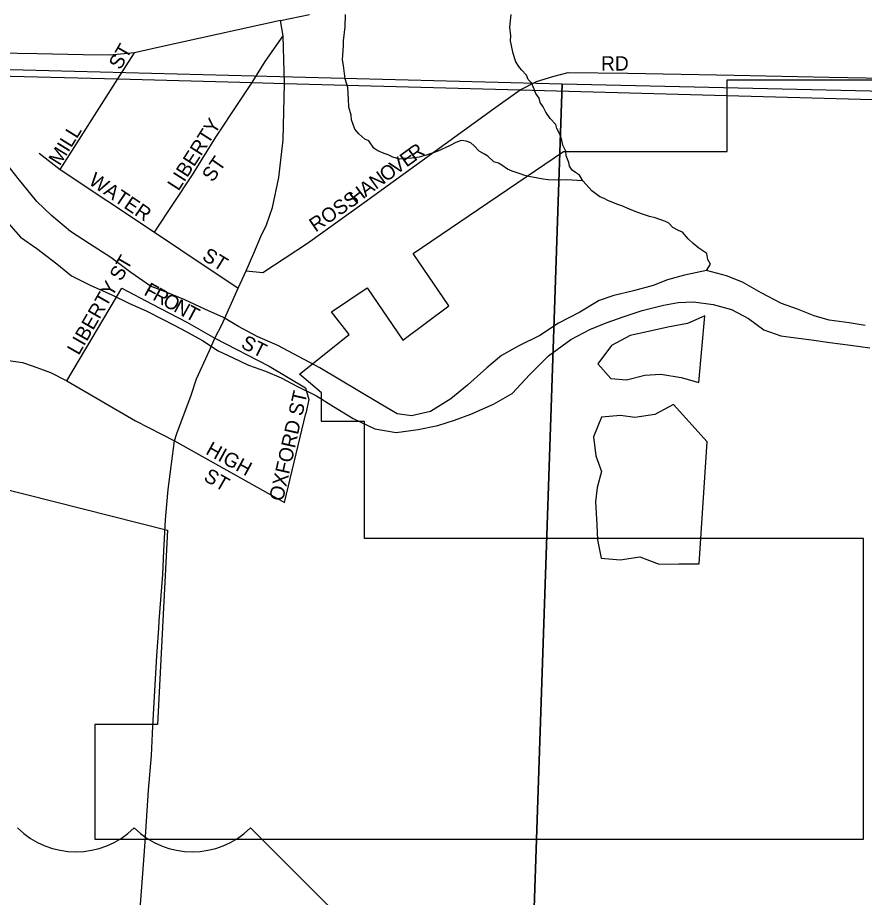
# Model space of a CAD drawing. Extents: x 0 to 34, y -2.3 to 22.
# Drawn here: x 5.063 to 5.622, y 19.85 to 20.43 of the extents above; entities that cross this region are included whole.
import ezdxf

# ---------------------------------------------------------------- set-up
doc = ezdxf.new("R2010")
doc.units = 0
for name, color, linetype in [('GM_X_City_Street', 7, 'Continuous'), ('GM_X_City_Street_Text', 7, 'Continuous'), ('GM_X_Corporation', 7, 'Continuous'), ('GM_X_Major_River', 7, 'Continuous'), ('GM_X_Minor_Lake', 7, 'Continuous'), ('GM_X_Minor_River', 7, 'Continuous'), ('GM_X_Section', 7, 'Continuous'), ('GM_X_State_Route', 7, 'Continuous'), ('GM_X_Township', 7, 'Continuous'), ('GM_X_US_Route', 7, 'Continuous'), ('GM_X_US_Shield', 7, 'Continuous')]:
    doc.layers.add(name, color=color, linetype=linetype)

msp = doc.modelspace()

# ---------------------------------------------------------------- linework, layer by layer
at = {"layer": 'GM_X_City_Street'}
for p, q in [((5.22626, 20.40134), (5.23811, 20.41837)), ((5.12886, 20.38988), (5.13988, 20.40723)), ((5.21759, 20.38745), (5.22626, 20.40134)), ((5.41612, 20.39156), (5.42625, 20.39407)), ((5.42625, 20.39407), (5.46566, 20.39379)), ((5.46566, 20.39379), (5.53591, 20.3924)), ((5.09095, 20.33019), (5.12886, 20.38988)), ((5.39462, 20.38262), (5.40534, 20.38813)), ((5.40534, 20.38813), (5.41612, 20.39156)), ((5.53591, 20.3924), (5.59864, 20.3911)), ((5.59864, 20.3911), (5.6453, 20.39026)), ((5.20883, 20.37426), (5.21759, 20.38745)), ((5.377, 20.37028), (5.39462, 20.38262)), ((5.19362, 20.3514), (5.20883, 20.37426)), ((5.29159, 20.30839), (5.377, 20.37028)), ((5.17831, 20.32653), (5.19362, 20.3514)), ((5.07696, 20.34097), (5.09095, 20.33019)), ((5.09095, 20.33019), (5.15323, 20.28879)), ((5.15323, 20.28879), (5.17831, 20.32653)), ((5.25414, 20.28162), (5.29159, 20.30839)), ((5.15323, 20.28879), (5.17052, 20.2771)), ((5.22477, 20.2622), (5.25414, 20.28162)), ((5.17052, 20.2771), (5.2084, 20.25188)), ((5.21369, 20.26322), (5.22477, 20.2622)), ((5.09518, 20.19062), (5.13161, 20.2519)), ((5.13161, 20.2519), (5.1517, 20.24133)), ((5.1517, 20.24133), (5.1744, 20.22938)), ((5.1744, 20.22938), (5.19304, 20.21874)), ((5.19304, 20.21874), (5.22879, 20.20028)), ((5.22879, 20.20028), (5.25287, 20.18608)), ((5.25287, 20.18608), (5.25512, 20.17828)), ((5.25512, 20.17828), (5.25303, 20.16909)), ((5.23903, 20.11025), (5.25303, 20.16909)), ((5.16643, 20.15101), (5.23903, 20.11025))]:
    msp.add_line(p, q, dxfattribs=at)
at = {"layer": 'GM_X_Corporation'}
for p, q in [((5.53117, 20.34201), (5.53118, 20.38935)), ((5.53118, 20.38935), (5.66754, 20.38934)), ((5.32391, 20.2747), (5.42322, 20.34201)), ((5.42322, 20.34201), (5.53117, 20.34201)), ((5.34741, 20.24023), (5.32391, 20.2747)), ((5.26993, 20.23619), (5.29361, 20.25198)), ((5.29361, 20.25198), (5.31711, 20.21751)), ((5.31711, 20.21751), (5.34741, 20.24023)), ((5.28163, 20.22123), (5.26993, 20.23619)), ((5.24886, 20.19501), (5.28163, 20.22123)), ((5.26347, 20.1828), (5.24886, 20.19501)), ((5.26347, 20.16386), (5.26347, 20.1828)), ((5.29188, 20.16386), (5.26347, 20.16386)), ((5.29187, 20.08661), (5.29188, 20.16386)), ((4.9456, 20.14662), (5.16168, 20.09204)), ((5.16168, 20.09204), (5.15509, 19.96389)), ((5.62136, 20.08659), (5.29187, 20.08661)), ((5.62134, 19.88812), (5.62136, 20.08659)), ((5.11381, 19.96389), (5.1138, 19.88814)), ((5.15509, 19.96389), (5.11381, 19.96389)), ((5.1138, 19.88814), (5.62134, 19.88812))]:
    msp.add_line(p, q, dxfattribs=at)
at = {"layer": 'GM_X_Major_River'}
for p, q in [((5.06314, 20.32417), (5.05352, 20.33652)), ((5.07536, 20.3091), (5.06314, 20.32417)), ((5.08505, 20.29978), (5.07536, 20.3091)), ((5.05385, 20.29776), (5.06461, 20.28539)), ((5.09775, 20.28926), (5.08505, 20.29978)), ((5.11011, 20.28103), (5.09775, 20.28926)), ((5.06461, 20.28539), (5.07547, 20.27794)), ((5.07547, 20.27794), (5.08855, 20.2678)), ((5.12436, 20.272), (5.11011, 20.28103)), ((5.13746, 20.26224), (5.12436, 20.272)), ((5.08855, 20.2678), (5.09827, 20.26)), ((5.09827, 20.26), (5.11106, 20.25366)), ((5.15057, 20.25323), (5.13746, 20.26224)), ((5.50298, 20.26044), (5.4919, 20.25725)), ((5.51749, 20.26356), (5.50298, 20.26044)), ((5.53071, 20.25987), (5.51749, 20.26356)), ((5.4919, 20.25725), (5.48232, 20.25364)), ((5.54127, 20.25585), (5.53071, 20.25987)), ((5.55366, 20.24876), (5.54127, 20.25585)), ((5.11106, 20.25366), (5.12461, 20.24768)), ((5.16074, 20.24922), (5.15057, 20.25323)), ((5.17318, 20.24403), (5.16074, 20.24922)), ((5.46933, 20.25011), (5.45634, 20.24696)), ((5.48232, 20.25364), (5.46933, 20.25011)), ((5.56719, 20.24165), (5.55366, 20.24876)), ((5.12461, 20.24768), (5.13665, 20.24174)), ((5.18635, 20.23806), (5.17318, 20.24403)), ((5.44677, 20.24374), (5.43407, 20.23602)), ((5.45634, 20.24696), (5.44677, 20.24374)), ((5.4988, 20.24229), (5.50907, 20.24284)), ((5.50907, 20.24284), (5.52196, 20.24105)), ((5.13665, 20.24174), (5.14757, 20.23696)), ((5.14757, 20.23696), (5.15884, 20.23103)), ((5.19877, 20.23249), (5.18635, 20.23806)), ((5.46327, 20.23314), (5.47513, 20.23708)), ((5.47513, 20.23708), (5.48927, 20.24059)), ((5.48927, 20.24059), (5.4988, 20.24229)), ((5.52196, 20.24105), (5.53405, 20.23777)), ((5.53405, 20.23777), (5.54532, 20.23184)), ((5.57775, 20.23801), (5.56719, 20.24165)), ((5.58868, 20.23361), (5.57775, 20.23801)), ((5.15884, 20.23103), (5.17125, 20.22469)), ((5.20853, 20.22659), (5.19877, 20.23249)), ((5.43407, 20.23602), (5.41985, 20.22871)), ((5.4514, 20.22883), (5.46327, 20.23314)), ((5.54532, 20.23184), (5.55543, 20.22441)), ((5.5985, 20.23075), (5.58868, 20.23361)), ((5.22093, 20.21988), (5.20853, 20.22659)), ((5.41985, 20.22871), (5.40752, 20.22061)), ((5.44067, 20.22449), (5.4514, 20.22883)), ((5.61176, 20.22896), (5.5985, 20.23075)), ((5.62236, 20.22722), (5.61176, 20.22896)), ((5.17125, 20.22469), (5.18477, 20.2172)), ((5.23448, 20.2139), (5.22093, 20.21988)), ((5.40752, 20.22061), (5.3937, 20.21367)), ((5.42799, 20.21791), (5.44067, 20.22449)), ((5.55543, 20.22441), (5.56674, 20.22038)), ((5.56674, 20.22038), (5.57659, 20.21904)), ((5.18477, 20.2172), (5.19527, 20.21053)), ((5.26229, 20.19927), (5.23448, 20.2139)), ((5.3937, 20.21367), (5.38217, 20.20745)), ((5.41332, 20.20719), (5.42799, 20.21791)), ((5.57659, 20.21904), (5.58682, 20.21769)), ((5.58682, 20.21769), (5.59895, 20.21592)), ((5.59895, 20.21592), (5.61259, 20.21412)), ((5.61259, 20.21412), (5.62547, 20.21234)), ((5.19527, 20.21053), (5.20505, 20.20577)), ((5.20505, 20.20577), (5.21521, 20.201)), ((5.38217, 20.20745), (5.3725, 20.19929)), ((5.4009, 20.19491), (5.41332, 20.20719)), ((5.21521, 20.201), (5.22653, 20.19697)), ((5.22653, 20.19697), (5.23669, 20.19258)), ((5.28856, 20.18354), (5.26229, 20.19927)), ((5.3725, 20.19929), (5.35971, 20.18778)), ((5.23669, 20.19258), (5.24721, 20.18705)), ((5.38924, 20.18223), (5.4009, 20.19491)), ((5.24721, 20.18705), (5.26, 20.18071)), ((5.35971, 20.18778), (5.34888, 20.17888)), ((5.26, 20.18071), (5.27125, 20.17364)), ((5.30095, 20.17607), (5.28856, 20.18354)), ((5.34888, 20.17888), (5.33541, 20.17042)), ((5.37693, 20.17527), (5.38924, 20.18223)), ((5.27125, 20.17364), (5.28439, 20.16577)), ((5.31333, 20.16897), (5.30095, 20.17607)), ((5.36197, 20.16874), (5.37693, 20.17527)), ((5.32281, 20.16764), (5.31333, 20.16897)), ((5.33541, 20.17042), (5.32281, 20.16764)), ((5.35125, 20.16478), (5.36197, 20.16874)), ((5.28439, 20.16577), (5.29869, 20.15902)), ((5.32718, 20.15843), (5.34015, 20.16121)), ((5.34015, 20.16121), (5.35125, 20.16478)), ((5.29869, 20.15902), (5.31269, 20.15645)), ((5.31269, 20.15645), (5.32718, 20.15843))]:
    msp.add_line(p, q, dxfattribs=at)
at = {"layer": 'GM_X_Minor_Lake'}
for p, q in [((5.51648, 20.23357), (5.50497, 20.22849)), ((5.51251, 20.18958), (5.51648, 20.23357)), ((5.492, 20.22609), (5.4794, 20.22331)), ((5.50497, 20.22849), (5.492, 20.22609)), ((5.46718, 20.22052), (5.45488, 20.21394)), ((5.4794, 20.22331), (5.46718, 20.22052)), ((5.45488, 20.21394), (5.44589, 20.20196)), ((5.44589, 20.20196), (5.45443, 20.19229)), ((5.45443, 20.19229), (5.46467, 20.19132)), ((5.46467, 20.19132), (5.47689, 20.19449)), ((5.47689, 20.19449), (5.48755, 20.19503)), ((5.48755, 20.19503), (5.5008, 20.19286)), ((5.5008, 20.19286), (5.51251, 20.18958)), ((5.49587, 20.17511), (5.48357, 20.16852)), ((5.51814, 20.15034), (5.49587, 20.17511)), ((5.46075, 20.16785), (5.44819, 20.16659)), ((5.47023, 20.16652), (5.46075, 20.16785)), ((5.48357, 20.16852), (5.47023, 20.16652)), ((5.44819, 20.16659), (5.44298, 20.15378)), ((5.44298, 20.15378), (5.44461, 20.14121)), ((5.51265, 20.06991), (5.51814, 20.15034)), ((5.44461, 20.14121), (5.44819, 20.13088)), ((5.44819, 20.13088), (5.44531, 20.1203)), ((5.44531, 20.1203), (5.44435, 20.11082)), ((5.44435, 20.11082), (5.44517, 20.09561)), ((5.44517, 20.09561), (5.44572, 20.08572)), ((5.44572, 20.08572), (5.44813, 20.07351)), ((5.46064, 20.0725), (5.47361, 20.07451)), ((5.47361, 20.07451), (5.48643, 20.06969)), ((5.44813, 20.07351), (5.46064, 20.0725)), ((5.48643, 20.06969), (5.49935, 20.0698)), ((5.49935, 20.0698), (5.51265, 20.06991))]:
    msp.add_line(p, q, dxfattribs=at)
at = {"layer": 'GM_X_Minor_River'}
for p, q in [((5.27897, 20.42419), (5.27916, 20.43254)), ((5.38773, 20.42414), (5.38868, 20.43247)), ((5.278, 20.41509), (5.27897, 20.42419)), ((5.38836, 20.41842), (5.38773, 20.42414)), ((5.38828, 20.415), (5.38836, 20.41842)), ((5.27739, 20.40561), (5.27792, 20.41206)), ((5.27792, 20.41206), (5.278, 20.41509)), ((5.38998, 20.40661), (5.38828, 20.415)), ((5.27732, 20.40257), (5.27739, 20.40561)), ((5.39176, 20.40124), (5.38998, 20.40661)), ((5.278, 20.39876), (5.27732, 20.40257)), ((5.39359, 20.39816), (5.39176, 20.40124)), ((5.27863, 20.39342), (5.278, 20.39876)), ((5.39544, 20.39583), (5.39359, 20.39816)), ((5.39878, 20.39233), (5.39544, 20.39583)), ((5.27893, 20.39), (5.27863, 20.39342)), ((5.2807, 20.38426), (5.27893, 20.39)), ((5.39986, 20.38964), (5.39878, 20.39233)), ((5.40209, 20.38731), (5.39986, 20.38964)), ((5.28128, 20.37664), (5.2807, 20.38426)), ((5.40389, 20.38309), (5.40209, 20.38731)), ((5.40497, 20.3804), (5.40389, 20.38309)), ((5.28154, 20.37132), (5.28128, 20.37664)), ((5.40718, 20.37731), (5.40497, 20.3804)), ((5.40787, 20.37425), (5.40718, 20.37731)), ((5.28294, 20.36597), (5.28154, 20.37132)), ((5.40971, 20.37154), (5.40787, 20.37425)), ((5.41153, 20.36808), (5.40971, 20.37154)), ((5.28325, 20.36292), (5.28294, 20.36597)), ((5.41447, 20.36383), (5.41153, 20.36808)), ((5.28539, 20.35679), (5.28325, 20.36292)), ((5.41818, 20.35994), (5.41447, 20.36383)), ((5.41888, 20.35726), (5.41818, 20.35994)), ((5.28798, 20.35369), (5.28539, 20.35679)), ((5.29208, 20.35016), (5.28798, 20.35369)), ((5.42069, 20.35342), (5.41888, 20.35726)), ((5.42213, 20.34958), (5.42069, 20.35342)), ((5.29471, 20.34896), (5.29208, 20.35016)), ((5.29803, 20.34432), (5.29471, 20.34896)), ((5.35211, 20.34791), (5.34788, 20.34574)), ((5.35557, 20.34934), (5.35211, 20.34791)), ((5.35898, 20.34888), (5.35557, 20.34934)), ((5.362, 20.34766), (5.35898, 20.34888)), ((5.36423, 20.34571), (5.362, 20.34766)), ((5.42281, 20.34615), (5.42213, 20.34958)), ((5.30064, 20.34235), (5.29803, 20.34432)), ((5.30479, 20.34073), (5.30064, 20.34235)), ((5.34019, 20.34213), (5.33712, 20.34106)), ((5.34788, 20.34574), (5.34019, 20.34213)), ((5.36757, 20.34221), (5.36423, 20.34571)), ((5.37095, 20.34022), (5.36757, 20.34221)), ((5.42462, 20.3423), (5.42281, 20.34615)), ((5.42493, 20.33926), (5.42462, 20.3423)), ((5.30743, 20.3399), (5.30479, 20.34073)), ((5.31044, 20.33831), (5.30743, 20.3399)), ((5.31497, 20.33706), (5.31044, 20.33831)), ((5.31764, 20.33737), (5.31497, 20.33706)), ((5.32297, 20.33762), (5.31764, 20.33737)), ((5.32793, 20.33825), (5.32297, 20.33762)), ((5.33253, 20.33966), (5.32793, 20.33825)), ((5.33712, 20.34106), (5.33253, 20.33966)), ((5.3732, 20.33903), (5.37095, 20.34022)), ((5.37729, 20.33512), (5.3732, 20.33903)), ((5.42672, 20.33465), (5.42493, 20.33926)), ((5.38032, 20.33429), (5.37729, 20.33512)), ((5.38257, 20.33309), (5.38032, 20.33429)), ((5.38631, 20.33034), (5.38257, 20.33309)), ((5.38933, 20.32913), (5.38631, 20.33034)), ((5.42705, 20.33237), (5.42672, 20.33465)), ((5.42889, 20.32966), (5.42705, 20.33237)), ((5.43113, 20.32808), (5.42889, 20.32966)), ((5.39385, 20.32749), (5.38933, 20.32913)), ((5.39762, 20.32626), (5.39385, 20.32749)), ((5.40027, 20.32543), (5.39762, 20.32626)), ((5.40633, 20.32452), (5.40027, 20.32543)), ((5.40973, 20.32368), (5.40633, 20.32452)), ((5.43376, 20.3265), (5.43113, 20.32808)), ((5.43595, 20.32265), (5.43376, 20.3265)), ((5.41315, 20.32321), (5.40973, 20.32368)), ((5.42151, 20.32301), (5.41315, 20.32321)), ((5.42532, 20.32329), (5.42151, 20.32301)), ((5.43595, 20.32265), (5.42532, 20.32329)), ((5.43818, 20.32031), (5.43595, 20.32265)), ((5.44188, 20.31604), (5.43818, 20.32031)), ((5.44711, 20.31211), (5.44188, 20.31604)), ((5.45013, 20.3109), (5.44711, 20.31211)), ((5.45238, 20.3097), (5.45013, 20.3109)), ((5.45841, 20.30727), (5.45238, 20.3097)), ((5.4618, 20.30605), (5.45841, 20.30727)), ((5.4667, 20.30403), (5.4618, 20.30605)), ((5.47047, 20.30241), (5.4667, 20.30403)), ((5.47461, 20.30079), (5.47047, 20.30241)), ((5.4799, 20.29914), (5.47461, 20.30079)), ((5.48368, 20.29829), (5.4799, 20.29914)), ((5.49047, 20.29584), (5.48368, 20.29829)), ((5.49272, 20.29464), (5.49047, 20.29584)), ((5.49532, 20.29192), (5.49272, 20.29464)), ((5.49908, 20.28992), (5.49532, 20.29192)), ((5.50171, 20.28872), (5.49908, 20.28992)), ((5.50542, 20.28445), (5.50171, 20.28872)), ((5.50877, 20.28132), (5.50542, 20.28445)), ((5.5125, 20.27819), (5.50877, 20.28132)), ((5.51774, 20.27464), (5.5125, 20.27819)), ((5.51841, 20.27083), (5.51774, 20.27464)), ((5.51749, 20.26356), (5.52024, 20.26774)), ((5.52024, 20.26774), (5.51841, 20.27083))]:
    msp.add_line(p, q, dxfattribs=at)
at = {"layer": 'GM_X_Section'}
for p, q in [((4.67462, 20.40621), (5.42234, 20.38658)), ((4.67462, 20.40621), (5.42234, 20.38658)), ((5.42234, 20.38658), (5.38725, 19.3604)), ((5.38725, 19.3604), (5.42234, 20.38658)), ((5.42234, 20.38658), (5.6658, 20.38106)), ((5.42234, 20.38658), (5.6658, 20.38106))]:
    msp.add_line(p, q, dxfattribs=at)
at = {"layer": 'GM_X_State_Route'}
for p, q in [((5.23628, 20.42846), (5.25551, 20.43233)), ((5.05669, 20.2041), (5.06597, 20.20276)), ((5.06597, 20.20276), (5.07312, 20.20035)), ((5.07312, 20.20035), (5.08437, 20.19606)), ((5.08437, 20.19606), (5.09518, 20.19062)), ((5.09518, 20.19062), (5.14063, 20.16418)), ((5.14063, 20.16418), (5.16643, 20.15101))]:
    msp.add_line(p, q, dxfattribs=at)
at = {"layer": 'GM_X_Township'}
for p, q in [((4.3985, 20.40982), (5.12886, 20.38988)), ((4.3985, 20.40982), (5.12886, 20.38988)), ((5.12886, 20.38988), (5.2176, 20.38745)), ((5.12886, 20.38988), (5.2176, 20.38745)), ((5.2176, 20.38745), (5.23899, 20.38687)), ((5.2176, 20.38745), (5.23899, 20.38687)), ((5.23899, 20.38687), (5.39461, 20.38262)), ((5.23899, 20.38687), (5.39461, 20.38262)), ((5.39461, 20.38262), (5.66673, 20.37519)), ((5.39461, 20.38262), (5.66673, 20.37519))]:
    msp.add_line(p, q, dxfattribs=at)
at = {"layer": 'GM_X_US_Route'}
for p, q in [((5.23628, 20.42846), (5.1954, 20.41954)), ((5.23811, 20.41837), (5.23628, 20.42846)), ((5.1954, 20.41954), (5.15648, 20.41082)), ((5.23899, 20.38687), (5.23811, 20.41837)), ((5.07555, 20.40656), (5.04777, 20.40685)), ((5.10594, 20.40575), (5.07555, 20.40656)), ((5.12378, 20.40556), (5.10594, 20.40575)), ((5.13988, 20.40723), (5.12378, 20.40556)), ((5.15648, 20.41082), (5.13988, 20.40723)), ((5.23813, 20.34968), (5.23899, 20.38687)), ((5.2353, 20.32481), (5.23813, 20.34968)), ((5.23112, 20.30514), (5.2353, 20.32481)), ((5.22711, 20.29352), (5.23112, 20.30514)), ((5.22344, 20.28592), (5.22711, 20.29352)), ((5.2188, 20.27484), (5.22344, 20.28592)), ((5.21369, 20.26322), (5.2188, 20.27484)), ((5.2084, 20.25188), (5.21369, 20.26322)), ((5.19761, 20.22765), (5.2084, 20.25188)), ((5.19304, 20.21874), (5.19761, 20.22765)), ((5.18934, 20.21058), (5.19304, 20.21874)), ((5.1809, 20.19191), (5.18934, 20.21058)), ((5.17724, 20.1811), (5.1809, 20.19191)), ((5.16795, 20.1558), (5.17724, 20.1811)), ((5.16643, 20.15101), (5.16795, 20.1558)), ((5.16216, 20.11888), (5.16643, 20.15101)), ((5.16056, 20.10163), (5.16216, 20.11888)), ((5.15919, 20.07844), (5.16032, 20.09897)), ((5.16032, 20.09897), (5.16056, 20.10163)), ((5.15857, 20.06284), (5.15919, 20.07844)), ((5.15627, 20.03216), (5.15857, 20.06284)), ((5.1559, 20.02723), (5.15627, 20.03216)), ((5.15467, 20.00926), (5.1559, 20.02723)), ((5.15282, 19.97827), (5.15467, 20.00926)), ((5.15209, 19.96267), (5.15282, 19.97827)), ((5.15118, 19.94327), (5.15209, 19.96267)), ((5.14923, 19.92059), (5.15118, 19.94327)), ((5.14734, 19.89322), (5.14923, 19.92059)), ((5.14666, 19.8833), (5.14734, 19.89322)), ((5.14544, 19.86557), (5.14666, 19.8833)), ((5.14266, 19.8276), (5.14544, 19.86557))]:
    msp.add_line(p, q, dxfattribs=at)
at = {"layer": 'GM_X_US_Shield'}
msp.add_line((5.27147, 19.8406), (5.21654, 19.89554), dxfattribs=at)
for centre in [(5.10119, 19.93477), (5.17809, 19.93477)]:
    msp.add_arc(centre, 0.05493, 225.573, 314.427, dxfattribs=at)

# ---------------------------------------------------------------- texts
at = {"layer": 'GM_X_City_Street_Text'}
for s, rotation, p in [('ST', 60.25385, (5.13059, 20.39538)), ('RD', 0.00001, (5.44797, 20.39544)), ('LIBERTY', 57.37927, (5.16897, 20.31545)), ('MILL', 58.17245, (5.09063, 20.3321)), ('E', 35.96693, (5.31951, 20.33132)), ('R', 35.93719, (5.3249, 20.33524)), ('ST', 55.30244, (5.19157, 20.32124)), ('V', 35.95184, (5.31276, 20.32643)), ('O', 35.96805, (5.30602, 20.32154)), ('WATER', 325.98209, (5.10897, 20.32097)), ('N', 35.95184, (5.29927, 20.31664)), ('H', 37.51795, (5.28599, 20.30669)), ('A', 36.16718, (5.29255, 20.31173)), ('ROSS', 34.59264, (5.25946, 20.28846)), ('ST', 328.39531, (5.18391, 20.27102)), ('LIBERTY ST', 60.16442, (5.10309, 20.20705)), ('F', 330.99051, (5.14551, 20.24772)), ('R', 330.99093, (5.15134, 20.24449)), ('O', 330.99152, (5.1579, 20.24085)), ('N', 330.98573, (5.16518, 20.23681)), ('T', 332.02585, (5.17264, 20.23268)), ('ST', 333.43495, (5.2096, 20.21276)), ('OXFORD ST', 77.22873, (5.2379, 20.11073)), ('HIGH', 331.26003, (5.18633, 20.14273)), ('ST', 330.25092, (5.18494, 20.12524))]:
    msp.add_text(s, height=0.00947, rotation=rotation, dxfattribs=at).set_placement(p)

doc.saveas('drawing.dxf')
